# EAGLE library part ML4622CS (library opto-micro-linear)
FIBER OPTIC DATA QUANTIZER
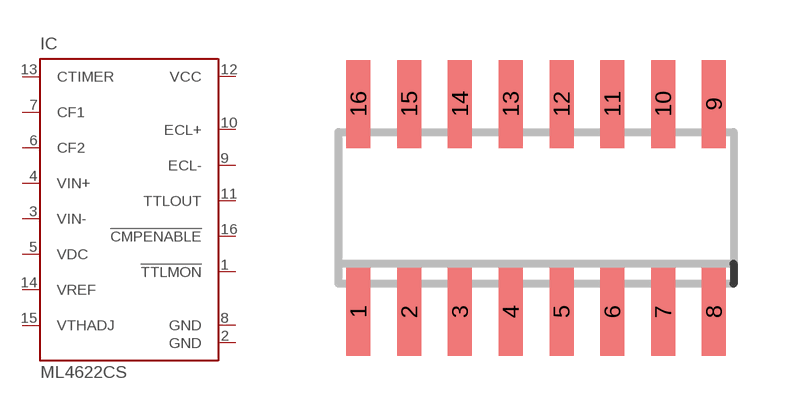
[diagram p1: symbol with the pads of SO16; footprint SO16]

Designator prefix IC

## ML4622CS (OC_FARNELL: unknown; OC_NEWARK: unknown)  [SO16]
1  !TTLMON  out
2  GND  pwr
3  VIN-  in
4  VIN+  in
5  VDC  pas
6  CF2  pas
7  CF1  pas
8  GND  pwr
9  ECL-  out
10  ECL+  out
11  TTLOUT  out
12  VCC  pwr
13  CTIMER  pas
14  VREF  in
15  VTHADJ  in
16  !CMPENABLE  in

## Footprint SO16 (pad centres in mm)
Small Outline package 150 mil
smd 0.6 x 2.2: 1 -4.445,-2.6; 2 -3.175,-2.6; 3 -1.905,-2.6; 4 -0.635,-2.6; 5 0.635,-2.6; 6 1.905,-2.6; 7 3.175,-2.6; 8 4.445,-2.6; 9 4.445,2.6; 10 3.175,2.6; 11 1.905,2.6; 12 0.635,2.6; 13 -0.635,2.6; 14 -1.905,2.6; 15 -3.175,2.6; 16 -4.445,2.6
